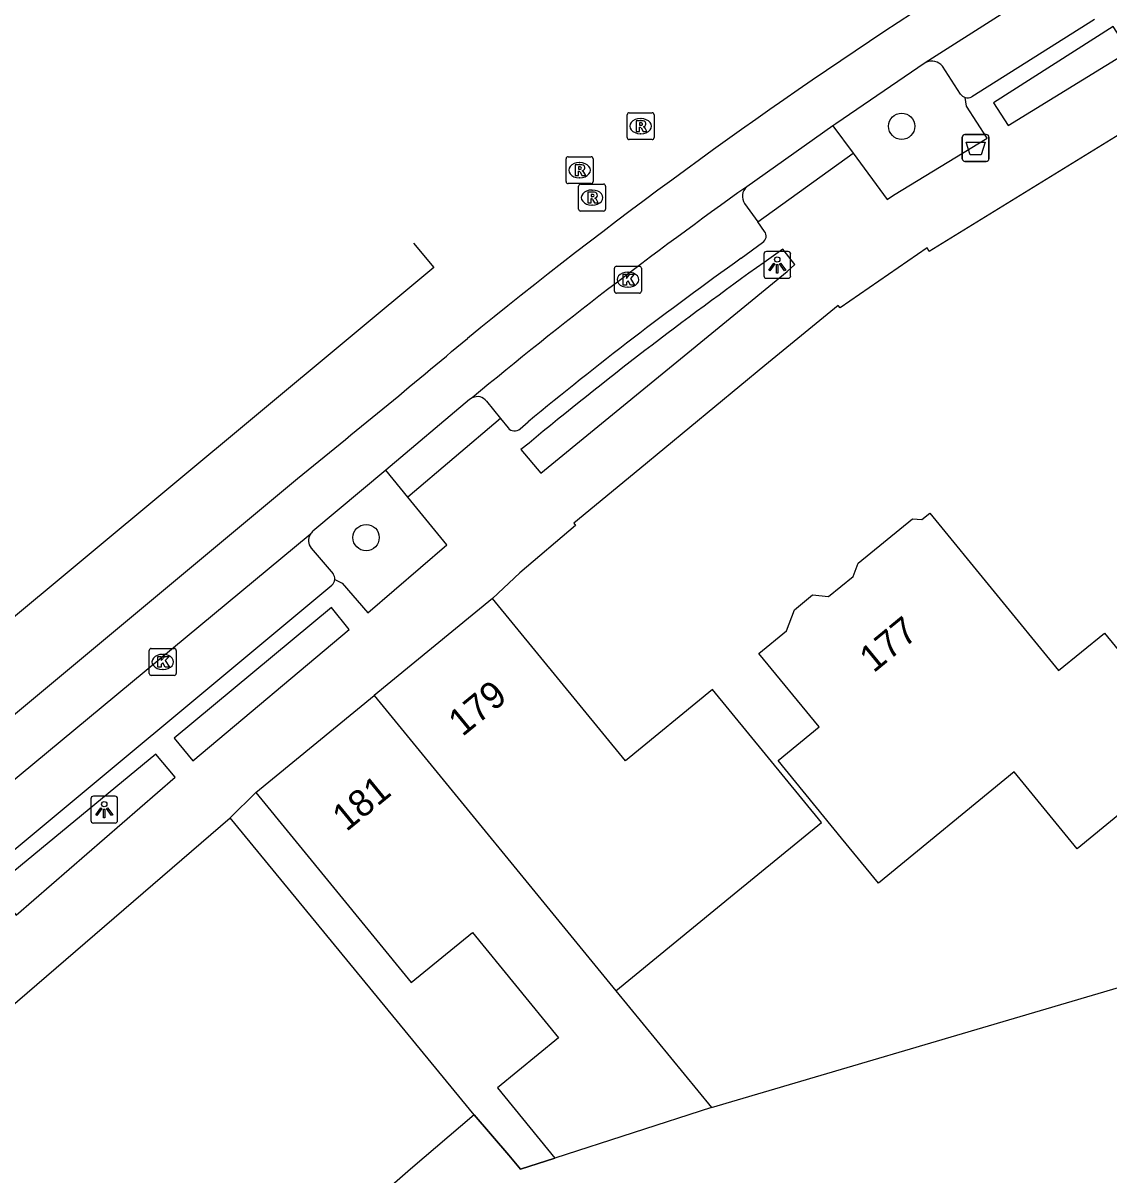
# Model space of a CAD drawing. Extents: x 159718 to 160783, y 383290 to 384030.
# Drawn here: x 159916.35 to 159956.7, y 383658.44 to 383701.23 of the extents above; entities that cross this region are included whole.
import ezdxf

# ---------------------------------------------------------------- set-up
doc = ezdxf.new("R2010")
doc.units = 0
for name, color, linetype in [('IMGEO_Afvalbak', 7, 'Continuous'), ('IMGEO_Boom', 7, 'Continuous'), ('IMGEO_Kolk', 7, 'Continuous'), ('IMGEO_Lichtpunt', 7, 'Continuous'), ('IMGEO_Muur', 7, 'Continuous'), ('IMGEO_Pand', 7, 'Continuous'), ('IMGEO_Pand_nummerreeks', 7, 'Continuous'), ('IMGEO_Parkeervlak_open', 7, 'Continuous'), ('IMGEO_Rijbaan_lokaal_gesloten', 7, 'Continuous'), ('IMGEO_Rijbaan_lokaal_open', 7, 'Continuous'), ('IMGEO_Rioolput', 7, 'Continuous'), ('IMGEO_Voetpad_open', 7, 'Continuous')]:
    doc.layers.add(name, color=color, linetype=linetype)

msp = doc.modelspace()

# ---------------------------------------------------------------- linework, layer by layer
at = {"layer": 'IMGEO_Afvalbak'}
for p, q in [((159951.345, 383697.091), (159952.135, 383697.091)), ((159952.135, 383697.091), (159951.345, 383697.091)), ((159951.245, 383696.191), (159951.245, 383696.991)), ((159951.245, 383696.991), (159951.245, 383696.191)), ((159952.235, 383696.991), (159952.235, 383696.191)), ((159952.235, 383696.191), (159952.235, 383696.991)), ((159952.135, 383696.091), (159951.345, 383696.091)), ((159951.345, 383696.091), (159952.135, 383696.091))]:
    msp.add_line(p, q, dxfattribs=at)
msp.add_lwpolyline([(159951.388, 383696.805), (159952.092, 383696.805), (159951.943, 383696.335), (159951.537, 383696.335), (159951.388, 383696.805)], dxfattribs=at)
for centre, start, end in [((159951.345, 383696.991), 90, 180), ((159951.345, 383696.991), 90, 180), ((159952.135, 383696.991), 0, 90), ((159952.135, 383696.991), 360, 90), ((159951.345, 383696.191), 180, 270), ((159951.345, 383696.191), 180, 270), ((159952.135, 383696.191), 270, 0), ((159952.135, 383696.191), 270, 0)]:
    msp.add_arc(centre, 0.1, start, end, dxfattribs=at)
at = {"layer": 'IMGEO_Boom'}
for centre in [(159948.994, 383697.395), (159929.094, 383682.115)]:
    msp.add_circle(centre, 0.489, dxfattribs=at)
at = {"layer": 'IMGEO_Kolk'}
for p, q in [((159938.322, 383691.269), (159938.322, 383692.121)), ((159938.397, 383692.195), (159939.249, 383692.195)), ((159938.81, 383691.975), (159938.835, 383691.975)), ((159939.323, 383692.121), (159939.323, 383691.269)), ((159939.249, 383691.195), (159938.397, 383691.195)), ((159938.833, 383691.415), (159938.808, 383691.415)), ((159921.039, 383677.072), (159921.039, 383677.924)), ((159921.114, 383677.998), (159921.966, 383677.998)), ((159922.04, 383677.924), (159922.04, 383677.072)), ((159921.527, 383677.778), (159921.552, 383677.778)), ((159921.966, 383676.998), (159921.114, 383676.998)), ((159921.55, 383677.218), (159921.525, 383677.218))]:
    msp.add_line(p, q, dxfattribs=at)
for points in [[(159938.322, 383691.269), (159938.322, 383692.121)], [(159938.397, 383692.195), (159939.249, 383692.195)], [(159939.323, 383692.121), (159939.323, 383691.269)], [(159938.643, 383691.895), (159938.766, 383691.895), (159938.766, 383691.744), (159938.896, 383691.895), (159939.06, 383691.895), (159938.914, 383691.744), (159939.067, 383691.495), (159938.915, 383691.495), (159938.83, 383691.659), (159938.766, 383691.592), (159938.766, 383691.495), (159938.643, 383691.495), (159938.643, 383691.895)], [(159939.249, 383691.195), (159938.397, 383691.195)], [(159921.039, 383677.072), (159921.039, 383677.924)], [(159921.114, 383677.998), (159921.966, 383677.998)], [(159922.04, 383677.924), (159922.04, 383677.072)], [(159921.36, 383677.698), (159921.483, 383677.698), (159921.483, 383677.547), (159921.613, 383677.698), (159921.777, 383677.698), (159921.631, 383677.547), (159921.784, 383677.298), (159921.632, 383677.298), (159921.547, 383677.462), (159921.483, 383677.395), (159921.483, 383677.298), (159921.36, 383677.298), (159921.36, 383677.698)], [(159921.966, 383676.998), (159921.114, 383676.998)]]:
    msp.add_lwpolyline(points, dxfattribs=at)
for centre, start, end in [((159938.399, 383692.119), 91.552, 178.448), ((159938.399, 383692.119), 91.552, 178.448), ((159939.247, 383692.119), 1.552, 88.448), ((159939.247, 383692.119), 1.552, 88.448), ((159938.399, 383691.271), 181.552, 268.448), ((159938.399, 383691.271), 181.552, 268.448), ((159939.247, 383691.271), 271.552, 358.448), ((159939.247, 383691.271), 271.552, 358.448), ((159921.116, 383677.922), 91.552, 178.448), ((159921.116, 383677.922), 91.552, 178.448), ((159921.964, 383677.922), 1.552, 88.448), ((159921.964, 383677.922), 1.552, 88.448), ((159921.116, 383677.074), 181.552, 268.448), ((159921.116, 383677.074), 181.552, 268.448), ((159921.964, 383677.074), 271.552, 358.448), ((159921.964, 383677.074), 271.552, 358.448)]:
    msp.add_arc(centre, 0.0765, start, end, dxfattribs=at)
for centre, major_axis, ratio, start_param, end_param in [((159938.809, 383691.695), (-0.387, 0.002), 0.722429, 4.712389, 7.853982), ((159938.834, 383691.695), (-0.39, 0.002), 0.717154, 1.570796, 4.712389), ((159921.526, 383677.498), (-0.387, 0.002), 0.722429, 4.712389, 7.853982), ((159921.551, 383677.498), (-0.39, 0.002), 0.717154, 1.570796, 4.712389)]:
    msp.add_ellipse(centre, major_axis=major_axis, ratio=ratio, start_param=start_param, end_param=end_param, dxfattribs=at)
at = {"layer": 'IMGEO_Lichtpunt'}
for p, q in [((159943.873, 383692.649), (159943.873, 383691.842)), ((159943.873, 383692.649), (159943.873, 383691.842)), ((159944.775, 383692.744), (159943.967, 383692.744)), ((159944.775, 383692.744), (159943.967, 383692.744)), ((159944.869, 383691.842), (159944.869, 383692.649)), ((159944.869, 383691.842), (159944.869, 383692.649)), ((159943.967, 383691.748), (159944.775, 383691.748)), ((159943.967, 383691.748), (159944.775, 383691.748)), ((159918.867, 383672.414), (159918.867, 383671.607)), ((159918.867, 383672.414), (159918.867, 383671.607)), ((159919.769, 383672.509), (159918.961, 383672.509)), ((159919.769, 383672.509), (159918.961, 383672.509)), ((159919.863, 383671.607), (159919.863, 383672.414)), ((159919.863, 383671.607), (159919.863, 383672.414)), ((159918.961, 383671.513), (159919.769, 383671.513)), ((159918.961, 383671.513), (159919.769, 383671.513))]:
    msp.add_line(p, q, dxfattribs=at)
for points in [[(159944.247, 383692.313), (159944.286, 383692.285), (159944.098, 383692.023), (159944.06, 383692.05), (159944.247, 383692.313)], [(159944.349, 383692.265), (159944.396, 383692.265), (159944.396, 383691.943), (159944.349, 383691.943), (159944.349, 383692.265)], [(159944.459, 383692.285), (159944.497, 383692.312), (159944.684, 383692.05), (159944.645, 383692.022), (159944.459, 383692.285)], [(159919.241, 383672.078), (159919.28, 383672.05), (159919.092, 383671.788), (159919.054, 383671.815), (159919.241, 383672.078)], [(159919.343, 383672.03), (159919.39, 383672.03), (159919.39, 383671.708), (159919.343, 383671.708), (159919.343, 383672.03)], [(159919.453, 383672.05), (159919.491, 383672.077), (159919.678, 383671.815), (159919.639, 383671.787), (159919.453, 383672.05)]]:
    msp.add_lwpolyline(points, dxfattribs=at)
for centre in [(159944.372, 383692.447), (159919.366, 383672.212)]:
    msp.add_circle(centre, 0.0994, dxfattribs=at)
for centre, start, end in [((159943.967, 383692.649), 90, 180), ((159943.967, 383692.649), 90, 180), ((159944.775, 383692.649), 0, 90), ((159944.775, 383692.649), 0, 90), ((159943.967, 383691.842), 180, 270), ((159943.967, 383691.842), 180, 270), ((159944.775, 383691.842), 270, 0), ((159944.775, 383691.842), 270, 360), ((159918.961, 383672.414), 90, 180), ((159918.961, 383672.414), 90, 180), ((159919.769, 383672.414), 0, 90), ((159919.769, 383672.414), 0, 90), ((159918.961, 383671.607), 180, 270), ((159918.961, 383671.607), 180, 270), ((159919.769, 383671.607), 270, 0), ((159919.769, 383671.607), 270, 360)]:
    msp.add_arc(centre, 0.0946, start, end, dxfattribs=at)
at = {"layer": 'IMGEO_Muur'}
for points in [[(159941.932, 383660.938), (159968.311, 383668.717)], [(159933.112, 383660.677), (159934.397, 383659.175)], [(159934.397, 383659.175), (159934.836, 383658.653), (159936.11, 383659.063)]]:
    msp.add_lwpolyline(points, dxfattribs=at)
at = {"layer": 'IMGEO_Pand'}
for points in [[(159947.189, 383680.672), (159947.373, 383681.161), (159949.395, 383682.817), (159949.746, 383682.782), (159950.04, 383683.022), (159954.824, 383677.181), (159956.533, 383678.569), (159958.961, 383675.607), (159958.821, 383674.187), (159957.886, 383673.42), (159958.337, 383672.871), (159955.515, 383670.557), (159953.176, 383673.411), (159948.135, 383669.278), (159946.764, 383670.947), (159944.4, 383673.832), (159945.924, 383675.08), (159943.687, 383677.811), (159944.711, 383678.65), (159945.008, 383679.437), (159945.677, 383679.985), (159946.278, 383679.926), (159947.189, 383680.672)], [(159933.79, 383679.853), (159929.393, 383676.251)], [(159938.379, 383665.283), (159942.775, 383668.883), (159946.009, 383671.532), (159941.966, 383676.468), (159938.732, 383673.819), (159933.79, 383679.853)], [(159924.993, 383672.648), (159929.393, 383676.251)], [(159929.393, 383676.251), (159938.379, 383665.283)], [(159924.993, 383672.648), (159930.773, 383665.591), (159933.042, 383667.449), (159936.248, 383663.537), (159933.975, 383661.675), (159936.11, 383659.063)], [(159896.105, 383647.633), (159924.039, 383671.703)], [(159933.112, 383660.677), (159924.039, 383671.703)], [(159938.379, 383665.283), (159941.932, 383660.938)], [(159933.112, 383660.677), (159930.75, 383658.654), (159928.75, 383656.911), (159929.967, 383655.515), (159927.937, 383653.745), (159927.747, 383654.002), (159925.242, 383651.86), (159924.196, 383652.991), (159921.738, 383650.872), (159917.025, 383646.81), (159914.578, 383644.701), (159915.553, 383643.507), (159913.041, 383641.356), (159912.033, 383642.515), (159909.393, 383640.252), (159908.776, 383640.972), (159907.807, 383642.101), (159905.987, 383640.536), (159903.808, 383638.662)], [(159941.932, 383660.938), (159936.11, 383659.063)]]:
    msp.add_lwpolyline(points, dxfattribs=at)
at = {"layer": 'IMGEO_Parkeervlak_open'}
for points in [[(159949.91, 383699.773), (159949.872, 383699.756)], [(159951.181, 383698.591), (159950.507, 383699.629)], [(159927.052, 383681.726), (159927.867, 383680.765)]]:
    msp.add_lwpolyline(points, dxfattribs=at)
for centre, radius, start, end in [((159950.106, 383699.275), 0.535, 41.4458, 111.4321), ((159951.454, 383698.779), 0.332, 214.4901, 252.1977), ((159927.383, 383682.005), 0.433, 147.9425, 220.1487), ((159927.641, 383680.581), 0.292, 355.9508, 39.234)]:
    msp.add_arc(centre, radius, start, end, dxfattribs=at)
at = {"layer": 'IMGEO_Rijbaan_lokaal_gesloten'}
for points in [[(159955.652, 383703.447), (159949.872, 383699.756)], [(159949.872, 383699.756), (159946.542, 383697.487), (159946.442, 383697.417)], [(159946.442, 383697.417), (159943.239, 383695.15)], [(159930.854, 383693.058), (159931.617, 383692.149), (159895.767, 383662.314)], [(159933.04, 383687.311), (159932.941, 383687.241), (159929.822, 383684.62)], [(159896.58, 383659.364), (159926.54, 383684.316)], [(159929.822, 383684.62), (159927.12, 383682.35)], [(159927.016, 383682.235), (159912.636, 383670.314)]]:
    msp.add_lwpolyline(points, dxfattribs=at)
for centre, radius, start, end in [((160054.936, 383539.834), 193.149, 123.12026, 129.19976), ((160042.002, 383556.099), 170.556, 125.38488, 129.70722), ((159674.424, 383997.283), 401.884, 308.85375, 310.0206), ((159927.397, 383681.995), 0.45, 127.9574, 147.7935)]:
    msp.add_arc(centre, radius, start, end, dxfattribs=at)
at = {"layer": 'IMGEO_Rijbaan_lokaal_open'}
for points in [[(159941.932, 383660.938), (159968.311, 383668.717)], [(159936.11, 383659.063), (159934.836, 383658.653), (159934.397, 383659.175), (159933.112, 383660.677)]]:
    msp.add_lwpolyline(points, dxfattribs=at)
at = {"layer": 'IMGEO_Rioolput'}
for p, q in [((159938.871, 383697.899), (159939.723, 383697.899)), ((159938.796, 383696.973), (159938.796, 383697.825)), ((159939.284, 383697.679), (159939.309, 383697.679)), ((159939.797, 383697.825), (159939.797, 383696.973)), ((159939.307, 383697.119), (159939.282, 383697.119)), ((159939.723, 383696.899), (159938.871, 383696.899)), ((159936.525, 383695.338), (159936.525, 383696.19)), ((159936.6, 383696.264), (159937.452, 383696.264)), ((159937.526, 383696.19), (159937.526, 383695.338)), ((159937.013, 383696.044), (159937.038, 383696.044)), ((159937.036, 383695.484), (159937.011, 383695.484)), ((159937.452, 383695.264), (159936.6, 383695.264)), ((159936.991, 383694.319), (159936.991, 383695.171)), ((159937.066, 383695.245), (159937.918, 383695.245)), ((159937.479, 383695.025), (159937.504, 383695.025)), ((159937.992, 383695.171), (159937.992, 383694.319)), ((159937.918, 383694.245), (159937.066, 383694.245)), ((159937.502, 383694.465), (159937.477, 383694.465))]:
    msp.add_line(p, q, dxfattribs=at)
for points in [[(159938.871, 383697.899), (159939.723, 383697.899)], [(159938.796, 383696.973), (159938.796, 383697.825)], [(159939.385, 383697.597), (159939.133, 383697.599), (159939.133, 383697.199)], [(159939.311, 383697.518), (159939.257, 383697.518), (159939.257, 383697.437)], [(159939.797, 383697.825), (159939.797, 383696.973)], [(159939.133, 383697.199), (159939.257, 383697.199), (159939.257, 383697.361), (159939.268, 383697.361)], [(159939.257, 383697.437), (159939.309, 383697.437)], [(159939.315, 383697.332), (159939.386, 383697.199), (159939.526, 383697.199), (159939.461, 383697.325)], [(159939.723, 383696.899), (159938.871, 383696.899)], [(159936.525, 383695.338), (159936.525, 383696.19)], [(159936.6, 383696.264), (159937.452, 383696.264)], [(159937.526, 383696.19), (159937.526, 383695.338)], [(159937.114, 383695.962), (159936.862, 383695.964), (159936.862, 383695.564)], [(159937.04, 383695.883), (159936.986, 383695.883), (159936.986, 383695.802)], [(159936.986, 383695.802), (159937.038, 383695.802)], [(159936.862, 383695.564), (159936.986, 383695.564), (159936.986, 383695.726), (159936.997, 383695.726)], [(159937.044, 383695.697), (159937.115, 383695.564), (159937.255, 383695.564), (159937.19, 383695.69)], [(159937.452, 383695.264), (159936.6, 383695.264)], [(159936.991, 383694.319), (159936.991, 383695.171)], [(159937.066, 383695.245), (159937.918, 383695.245)], [(159937.58, 383694.943), (159937.328, 383694.945), (159937.328, 383694.545)], [(159937.992, 383695.171), (159937.992, 383694.319)], [(159937.328, 383694.545), (159937.452, 383694.545), (159937.452, 383694.707), (159937.463, 383694.707)], [(159937.506, 383694.864), (159937.452, 383694.864), (159937.452, 383694.783)], [(159937.452, 383694.783), (159937.504, 383694.783)], [(159937.51, 383694.678), (159937.581, 383694.545), (159937.721, 383694.545), (159937.656, 383694.671)], [(159937.918, 383694.245), (159937.066, 383694.245)]]:
    msp.add_lwpolyline(points, dxfattribs=at)
for centre, radius, start, end in [((159938.873, 383697.823), 0.0765, 91.552, 178.448), ((159938.873, 383697.823), 0.0765, 91.552, 178.448), ((159939.721, 383697.823), 0.0765, 1.552, 88.448), ((159939.721, 383697.823), 0.0765, 1.552, 88.448), ((159939.317, 383697.422), 0.0964, 77.0061, 93.1865), ((159939.331, 383697.479), 0.0378, 276.6634, 79.6772), ((159939.384, 383697.487), 0.109, 350.3612, 89.416), ((159939.382, 383697.487), 0.112, 277.5842, 350.9817), ((159939.267, 383697.308), 0.0533, 26.0293, 88.6989), ((159939.293, 383697.626), 0.19, 274.7715, 282.9687), ((159939.366, 383697.272), 0.108, 29.5134, 73.7905), ((159938.873, 383696.975), 0.0765, 181.552, 268.448), ((159938.873, 383696.975), 0.0765, 181.552, 268.448), ((159939.721, 383696.975), 0.0765, 271.552, 358.448), ((159939.721, 383696.975), 0.0765, 271.552, 358.448), ((159936.602, 383696.188), 0.0765, 91.552, 178.448), ((159936.602, 383696.188), 0.0765, 91.552, 178.448), ((159937.45, 383696.188), 0.0765, 1.552, 88.448), ((159937.45, 383696.188), 0.0765, 1.552, 88.448), ((159937.022, 383695.991), 0.19, 274.7715, 282.9687), ((159937.046, 383695.787), 0.0964, 77.0061, 93.1865), ((159937.06, 383695.844), 0.0378, 276.6634, 79.6772), ((159937.113, 383695.852), 0.109, 350.3612, 89.416), ((159937.111, 383695.852), 0.112, 277.5842, 350.9817), ((159936.602, 383695.34), 0.0765, 181.552, 268.448), ((159936.602, 383695.34), 0.0765, 181.552, 268.448), ((159936.996, 383695.673), 0.0533, 26.0293, 88.6989), ((159937.095, 383695.637), 0.108, 29.5134, 73.7905), ((159937.45, 383695.34), 0.0765, 271.552, 358.448), ((159937.45, 383695.34), 0.0765, 271.552, 358.448), ((159937.068, 383695.169), 0.0765, 91.552, 178.448), ((159937.068, 383695.169), 0.0765, 91.552, 178.448), ((159937.579, 383694.833), 0.109, 350.3612, 89.416), ((159937.916, 383695.169), 0.0765, 1.552, 88.448), ((159937.916, 383695.169), 0.0765, 1.552, 88.448), ((159937.462, 383694.654), 0.0533, 26.0293, 88.6989), ((159937.488, 383694.972), 0.19, 274.7715, 282.9687), ((159937.512, 383694.768), 0.0964, 77.0061, 93.1865), ((159937.526, 383694.825), 0.0378, 276.6634, 79.6772), ((159937.577, 383694.833), 0.112, 277.5842, 350.9817), ((159937.561, 383694.618), 0.108, 29.5134, 73.7905), ((159937.068, 383694.321), 0.0765, 181.552, 268.448), ((159937.068, 383694.321), 0.0765, 181.552, 268.448), ((159937.916, 383694.321), 0.0765, 271.552, 358.448), ((159937.916, 383694.321), 0.0765, 271.552, 358.448)]:
    msp.add_arc(centre, radius, start, end, dxfattribs=at)
for centre, major_axis, ratio, start_param, end_param in [((159939.283, 383697.399), (-0.387, 0.002), 0.722429, 4.712389, 7.853982), ((159939.308, 383697.399), (-0.39, 0.002), 0.717154, 1.570796, 4.712389), ((159937.012, 383695.764), (-0.387, 0.002), 0.722429, 4.712389, 7.853982), ((159937.037, 383695.764), (-0.39, 0.002), 0.717154, 1.570796, 4.712389), ((159937.478, 383694.745), (-0.387, 0.002), 0.722429, 4.712389, 7.853982), ((159937.503, 383694.745), (-0.39, 0.002), 0.717154, 1.570796, 4.712389)]:
    msp.add_ellipse(centre, major_axis=major_axis, ratio=ratio, start_param=start_param, end_param=end_param, dxfattribs=at)
at = {"layer": 'IMGEO_Voetpad_open'}
for points in [[(159956.163, 383701.357), (159951.603, 383698.483)], [(159956.855, 383701.103), (159952.41, 383698.269), (159952.952, 383697.421), (159957.446, 383700.188), (159956.855, 383701.103)], [(159947.193, 383696.392), (159948.453, 383694.673), (159948.69, 383694.836), (159952.167, 383696.952), (159951.404, 383698.14), (159951.353, 383698.463)], [(159957.229, 383697.292), (159957.096, 383697.206), (159957.105, 383697.103), (159950.013, 383692.747), (159949.935, 383692.877), (159946.711, 383690.646), (159946.639, 383690.738), (159943.91, 383688.504), (159939.271, 383684.671), (159936.81, 383682.656), (159936.875, 383682.563), (159934.805, 383680.811), (159933.79, 383679.853)], [(159946.442, 383697.417), (159947.193, 383696.392)], [(159943.645, 383693.843), (159947.193, 383696.392)], [(159943.158, 383694.524), (159943.645, 383693.843)], [(159943.897, 383693.49), (159943.645, 383693.843)], [(159935.581, 383684.509), (159944.741, 383691.997), (159945.026, 383692.256), (159944.577, 383692.825), (159943.881, 383692.337)], [(159943.031, 383692.493), (159943.822, 383693.083)], [(159933.566, 383687.179), (159934.084, 383686.541)], [(159934.084, 383686.541), (159930.641, 383683.618)], [(159934.084, 383686.541), (159934.369, 383686.189)], [(159934.816, 383686.155), (159935.112, 383686.413)], [(159935.147, 383685.625), (159934.845, 383685.384), (159935.581, 383684.509)], [(159930.641, 383683.618), (159929.822, 383684.62)], [(159927.932, 383680.56), (159928.21, 383680.417), (159929.154, 383679.32), (159932.089, 383681.847), (159930.641, 383683.618)], [(159914.443, 383669.217), (159927.825, 383680.354)], [(159921.96, 383674.661), (159922.652, 383673.818), (159928.465, 383678.706), (159927.803, 383679.515), (159921.96, 383674.661)], [(159921.285, 383674.068), (159915.253, 383669.102), (159916.095, 383668.088), (159922.002, 383673.22), (159921.285, 383674.068)], [(159924.039, 383671.703), (159924.993, 383672.648)]]:
    msp.add_lwpolyline(points, dxfattribs=at)
for centre, radius, start, end in [((159951.454, 383698.773), 0.326, 251.9541, 297.1938), ((159943.544, 383694.792), 0.47, 130.4362, 214.8184), ((159943.689, 383693.318), 0.27, 299.5775, 39.5404), ((160024.59, 383578.068), 140.516, 125.48021, 129.552), ((160032.038, 383568.584), 151.942, 125.46465, 129.61926), ((159933.223, 383686.927), 0.425, 36.3009, 115.5241), ((159934.61, 383686.4), 0.321, 221.2758, 310.0248), ((159927.642, 383680.58), 0.291, 309.0439, 356.0598)]:
    msp.add_arc(centre, radius, start, end, dxfattribs=at)

# ---------------------------------------------------------------- texts
at = {"layer": 'IMGEO_Pand_nummerreeks'}
for s, rotation, p in [('177', 39.3601, (159947.949, 383677.064)), ('179', 39.3164, (159932.673, 383674.698)), ('181', 39.3185, (159928.363, 383671.169))]:
    msp.add_text(s, height=1, rotation=rotation, dxfattribs=at).set_placement(p)

doc.saveas('drawing.dxf')
